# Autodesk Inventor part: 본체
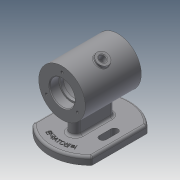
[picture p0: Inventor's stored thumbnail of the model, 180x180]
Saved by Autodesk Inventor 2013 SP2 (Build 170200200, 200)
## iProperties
Created: 2022-02
Part Number: 본체
Material: Generic
Document SubType Name: Modeling
Designer: a
Density: 1 g/cm^3
Author: a
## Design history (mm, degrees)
sketch "스케치1"
  geometry: L1 (-36, 0)-(36, 0); L2 (-36, 0)-(-36, 30); L3 (-36, 30)-(36, 30); L4 (36, 30)-(36, 0); L5 (-36, 16)-(-24, 16); L6 (-24, 16)-(-24, 14); L7 (-24, 14)-(-20, 14); L8 (-20, 14)-(-20, 25); L9 (-20, 25)-(20, 25); L10 (20, 25)-(20, 14); L11 (20, 14)-(24, 14); L12 (24, 14)-(24, 16); L13 (24, 16)-(36, 16); 2 further points
  constraints: 26 end point, 7 parallel, 4 perpendicular, 2 point on line, 1 coincident, 1 collinear, 1 horizontal, 1 midpoint
  dimensions: "d0" = 72 distance of L1.start L1.end; "d1" = 60 diameter of L3 L1; "d3" = 32 diameter of L5 L1; "d4" = 28 diameter of L7 L1; "d5" = 50 diameter of L9 L1; "d6" = 28 diameter of L11 L1; "d7" = 32 diameter of L13 L1; "d8" = 12 distance between parallel lines of L2 L6; "d9" = 40 distance between parallel lines of L10 L8; "d10" = 12 distance between parallel lines of L4 L12; "d11" = 4 distance between parallel lines of L6 L8
revolve "회전1" sketch "스케치1" stored, may be unused: angle "d12" = 90 deg
fillet "모깎기1" dims "d13" = 3
fillet "모깎기2" dims "d14" = 0.3
chamfer "모따기1" distance "d15" = 1; stored, may be unused: second distance "d16" = 2, angle "d17" = 45 deg
node "작업 평면1"
sketch "스케치2"
  geometry: C1 r 52 at (0, 0); 1 further point
  constraints: 1 centre point, 1 coincident
  dimensions: "d19" = 104 diameter of C1
extrude "돌출1" join sketch "스케치2" distance "d20" = 10; taper "d21" = 0 deg
sketch "스케치3"
  geometry: L1 (-35.496, 38)-(35.496, 38); L2 (-35.496, -38)-(35.496, -38); A1 r 52 centre (0, 0) between (-35.496, 38) and (35.496, 38) reference
  constraints: 4 end point, 4 point on circle, 1 horizontal, 1 parallel
  dimensions: "d22" = 76 distance between parallel lines of L2 L1; "d23" = 38 distance from line of L2 A1.centre
extrude "돌출2" cut sketch "스케치3" stored distance "d24" = 10; taper "d25" = 0 deg
sketch "스케치4"
  geometry: L1 (-19, 7)-(19, 7); L2 (19, 7)-(19, -7); L3 (19, -7)-(-19, -7); L4 (-19, -7)-(-19, 7); L5 (-19, 7)-(19, -7); L6 (19, 7)-(-19, -7); C1 r 7 at (19, 0); C2 r 7 at (-19, 0); A1 r 52 centre (0, 0) between (35.496, -38) and (35.496, 38) reference
  constraints: 12 end point, 4 midpoint, 2 centre point, 2 parallel, 1 horizontal, 1 perpendicular
  dimensions: "d26" = 38 distance of L2.end L3.end; "d27" = 14 distance of L1.end L2.end; "d28" = 14 diameter of C1; "d29" = 14 diameter of C2
extrude "돌출3" join sketch "스케치4" stored distance "d30" = 10; taper "d31" = 0 deg
sketch "스케치5"
  geometry: L1 (0, 0)-(0, 24); L2 (-7.5, 28.5)-(7.5, 28.5); L3 (7.5, 28.5)-(7.5, 19.5); L4 (7.5, 19.5)-(-7.5, 19.5); L5 (-7.5, 19.5)-(-7.5, 28.5); L6 (-7.5, 28.5)-(7.5, 19.5); L7 (7.5, 28.5)-(-7.5, 19.5); C1 r 4.5 at (7.5, 24); C2 r 4.5 at (-7.5, 24); A1 r 52 centre (0, 0) between (-35.496, 38) and (-35.496, -38) reference; A2 r 52 centre (0, 0) between (35.496, -38) and (35.496, 38) reference; 1 further point
  constraints: 14 end point, 5 midpoint, 2 centre point, 2 parallel, 1 horizontal, 1 perpendicular, 1 vertical alignment
  dimensions: "d34" = 24 distance of L1.start L1.end; "d35" = 15 distance of L3.end L4.end; "d36" = 9 distance of L2.end L3.end; "d37" = 9 diameter of C1; "d38" = 9 diameter of C2
extrude "돌출4" cut sketch "스케치5" stored distance "d39" = 10; taper "d40" = 0 deg
sketch "스케치6"
  geometry: L1 (0, 0)-(28.579, 16.5); L2 (0, 0)-(33, 0); C1 r 30 at (0, 0) reference; 2 further points
  constraints: 4 end point, 1 coincident, 1 equal length, 1 horizontal
  dimensions: "d41" = 33 distance of L1.start L1.end; "d42" = 30 deg angle of L2 L1
node "작업 평면2"
sketch "스케치7"
  geometry: C1 r 8 at (0, 0); 2 further points
  constraints: 2 coincident, 1 centre point
  dimensions: "d43" = 16 diameter of C1
extrude "돌출5" join sketch "스케치7" stored distance "d44" = 10; taper "d45" = 0 deg
sketch "스케치8"
  geometry: C1 r 8 at (0, 0) reference; 1 further point
  constraints: 1 coincident
hole "구멍1" sketch "스케치8" at (0, 0) diameter "d46" = 8; stored, may be unused: countersink angle "d50" = 90 deg, drill point angle "d52" = 0 deg; dims "d47" = 6, "d48" = 4, "d49" = 2, "d51" = 8
fillet "모깎기3" dims "d53" = 1
sketch "스케치9"
  geometry: C1 r 30 at (0, 0) reference; 1 further point
  constraints: 1 vertical alignment
  dimensions: "d57" = 23 distance of point (0, 23) C1.centre
hole "구멍2" sketch "스케치9" at (0, 23) diameter "d58" = 3.242; stored, may be unused: countersink angle "d62" = 90 deg, drill point angle "d64" = 118 deg; dims "d59" = 8, "d60" = 4, "d61" = 2, "d63" = 10
fillet "모깎기4" dims "d68" = 3
fillet "모깎기5" dims "d69" = 3
sketch "스케치10"
  geometry: L1 (-34.293, 35)-(34.293, 35) reference; L2 (34.293, -35)-(-34.293, -35) reference; L3 (-7.5, -19.5)-(7.5, -19.5) reference; L4 (7.5, -28.5)-(-7.5, -28.5) reference; L5 (-7.5, 28.5)-(7.5, 28.5) reference; L6 (7.5, 19.5)-(-7.5, 19.5) reference; L7 (19, 10)-(-19, 10) reference; L8 (-19, -10)-(19, -10) reference; C1 r 42.5 at (0, 0); A1 r 49 centre (0, 0) between (-34.293, 35) and (-34.293, -35) reference; A2 r 49 centre (0, 0) between (34.293, -35) and (34.293, 35) reference; A3 r 4.5 centre (7.5, -24) between (7.5, -28.5) and (7.5, -19.5) reference; A4 r 4.5 centre (-7.5, -24) between (-7.5, -19.5) and (-7.5, -28.5) reference; A5 r 4.5 centre (7.5, 24) between (7.5, 19.5) and (7.5, 28.5) reference; A6 r 4.5 centre (-7.5, 24) between (-7.5, 28.5) and (-7.5, 19.5) reference; A7 r 10 centre (19, 0) between (19, -10) and (19, 10) reference; A8 r 10 centre (-19, 0) between (-19, 10) and (-19, -10) reference
  constraints: 1 centre point, 1 coincident
  dimensions: "d70" = 85 diameter of C1
sketch "스케치11"
  geometry: C1 r 42.5 at (0, 0) reference
  constraints: 1 other
feature "엠보싱1" sketch "스케치11" dims "d0" = 72, "d1" = 60, "d3" = 32, "d4" = 28, "d5" = 50, "d6" = 28, "d7" = 32, "d8" = 12, "d9" = 40, "d10" = 12, "d11" = 4, "d14" = 0.3, "d71" = 0.5, "d72" = 0
fillet "모깎기6" dims "d73" = 3
fillet "모깎기7" dims "d74" = 1
node "솔리드1"
mirror "대칭1"
pattern_circular "원형 패턴1" dims angle "d66" = 360 deg
mirror "대칭2"
other parameters: "d18" = -62
